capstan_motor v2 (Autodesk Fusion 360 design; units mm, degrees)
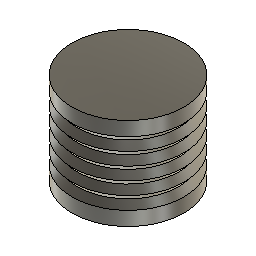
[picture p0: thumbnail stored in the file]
parameter "teeth" = 1
sketch "Sketch1" plane through (0, 0, 0) normal (0, 0, 1) x axis (1, 0, 0)
  circle C1 centre (0, 0) radius 10.936
  point P1 (0, 0)
  point P2 (0, 0)
  coincident P1 P2
  dimension "d1" diameter C1 = 21.872 (= "20.372 mm + 2 * teeth - 0.5 mm")
extrude "Extrude1" new body sketch "Sketch1" + "Sketch2" profile of S1:C1 distance 18
sketch "Sketch2" plane through (0, 0, 9) normal (0, 0, 1) x axis (-1, 0, 0)
  circle C1 centre (0, 0) radius 10.936
  circle C2 centre (0, 0) radius 2.52
  concentric C1 C2
  dimension "d4" diameter C2 = 5.04
extrude "Extrude2" cut sketch "Sketch2" profile of C2 against normal blind 26
sketch "Sketch3" plane through (0, 0, 0) normal (0, 1, 0) x axis (1, 0, 0)
  line L1 (10.936, -9) -> (-10.936, -9)
  line L2 (10.936, 9) -> (-10.936, 9)
  line L3 (10.936, 9) -> (10.936, -9)
  line L4 (9.936, 0) -> (10.936, -1.25)
  line L5 (10.936, 1.25) -> (9.936, 0)
  line L6 (10.936, -1.25) -> (10.936, 1.25)
  point P3 (10.936, -9)
  point P6 (10.936, -9)
  point P5 (10.936, 9)
  point P7 (10.936, 9)
  point P8 (10.936, -1.25)
  point P10 (10.936, 1.25)
  point P11 (10.936, 0)
  point P1 (0, 0)
  point P9 (9.936, 0)
  coincident P3 P6
  coincident P5 P7
  coincident L3 P8
  coincident L3 P10
  midpoint L6 P11
  horizontal P1 P11
  horizontal P9 P11
  dimension "d7" distance P8 P10 = 2.5
  dimension "d8" distance P9 P10 = 1 (= "teeth")
revolve "Revolve1" sketch "Sketch3" AlongAngle 360
rectangular_pattern "R-Pattern1" sketch "Sketch2" uSpaceDistance 2.5 vSpaceDistance 0
work_plane "WorkPlane1" sketch "Sketch2" AlongDistance -11
sketch "Sketch4" plane through (0, 0, 9) normal (0, 0, 1) x axis (-1, 0, 0)
  circle C1 centre (0, 0) radius 2.52
  circle C2 centre (0, 0) radius 10.936
extrude "Extrude3" add sketch "Sketch4" profile of C1 to an object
